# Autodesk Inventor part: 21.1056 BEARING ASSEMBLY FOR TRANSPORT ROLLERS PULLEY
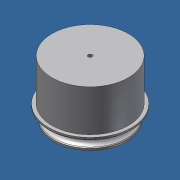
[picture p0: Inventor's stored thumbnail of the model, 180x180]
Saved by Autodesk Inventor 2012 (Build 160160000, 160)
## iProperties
Created: 2007-07
Part Number: 21.1056 BEARING ASSEMBLY FOR TRANSPORT ROLLERS PULLEY
Material: PVC-U
Document SubType Name: Modeling
Designer: Andy Moles
Density: 1.4 g/cm^3
Mass: 75.8275 g
Surface Area: 99.9703 cm^2
Volume: 54.1625 cm^3
Author: Andy Moles
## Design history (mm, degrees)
feature "Base1"
body "Solid1"
